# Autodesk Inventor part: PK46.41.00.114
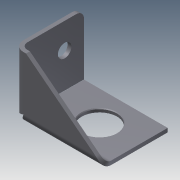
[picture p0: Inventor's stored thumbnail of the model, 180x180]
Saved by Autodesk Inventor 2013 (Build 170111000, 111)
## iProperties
Created: 2005-07
Part Number: PK46.41.00.114
Material: Steel, Mild
Document SubType Name: Листовой материал
Designer: PVitaliy
Manufacturer: Standard
Standards Organization: Custom
Density: 7.86 g/cm^3
Sheet Metal Rule: По умолчанию
Author: PVitaliy
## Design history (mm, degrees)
node "ФлнОтгиб1"
hole "Отверстие1" diameter "d11" = 10.5; stored, may be unused: countersink angle "d15" = 90 deg, drill point angle "d17" = 118 deg; dims "d9" = 15, "d10" = 20, "d12" = 6, "d13" = 4, "d14" = 2, "d16" = 3 (= Толщина)
feature "Вырез1" dims "d20" = 3 (= Толщина), "d21" = 0
node "Фланец1"
feature "Угловое скругление1" dims "d29" = 6
hole "Отверстие2" diameter "d32" = 27; stored, may be unused: countersink angle "d36" = 90 deg, drill point angle "d38" = 118 deg; dims "d30" = 23, "d31" = 30, "d33" = 6, "d34" = 4, "d35" = 2, "d37" = 3 (= Толщина)
feature "Угол1" dims "d39" = 12 (= Размер_высечки), "d40" = 5 (= Радиус_гибки), "d41" = 0.1, "d42" = 0, "Толщина" = 3
chamfer "Фаска1" distance "d43" = 0.5; stored, may be unused: second distance "d44" = 2, angle "d45" = 45 deg
body "Solid1"
sketch "Эскиз2"
  geometry: L1 (0, 0)-(68, 0); L2 (0, 0)-(0, 52)
  constraints: 4 end point, 1 horizontal, 1 vertical, 1 other
  dimensions: "d0" = 68 distance of L1.start L1.end; "d1" = 52 distance of L1.start L2.end
feature "Плакирование1" dims "d2" = 50, "d3" = 3 (= Ширина_просечки), "d5" = 6 (= Минимальный_остаток), "d7" = 5 (= Радиус_гибки), "d8" = 3, "Толщина" = 3
feature "Изгиб1" dims "d3" = 3 (= Ширина_просечки), "d4" = 1.5 (= Глубина_просечки), "d5" = 6 (= Минимальный_остаток), "d6" = 5 (= Радиус_гибки), "d7" = 5 (= Радиус_гибки), "d8" = 3, "Толщина" = 3, "Зазор_стыка" = 0.01
sketch "Эскиз3"
  geometry: L1 (0, 0)-(-60, 0) reference; L2 (0, 0)-(0, 50) reference; L3 (0, 50)-(-60, 50) reference; L4 (0, 5)-(-58, 50); L5 (-68, 0)-(-68, 50) reference
  constraints: 2 end point, 2 point on line
  dimensions: "d18" = 5 distance from line of L4.start L1; "d19" = 10 distance from line of L4.end L5
sketch "Эскиз4"
  geometry: L1 through (30, 0) direction (1, -1.85e-17); L2 (60, 0)-(60, 49); L3 (60, 49)-(0, 49); L4 through (0, 24.5) direction (0, -1)
  constraints: 6 end point, 1 horizontal, 1 perpendicular, 1 vertical
feature "Плакирование2" dims "d22" = 3 (= Ширина_просечки), "d24" = 6 (= Минимальный_остаток), "d26" = 49, "d27" = 90 deg, "d28" = 5 (= Радиус_гибки), "Толщина" = 3
feature "Изгиб2" dims "d22" = 3 (= Ширина_просечки), "d23" = 1.5 (= Глубина_просечки), "d24" = 6 (= Минимальный_остаток), "d25" = 5 (= Радиус_гибки), "d26" = 49, "d27" = 90 deg, "d28" = 5 (= Радиус_гибки), "Толщина" = 3, "Зазор_стыка" = 0.01
other parameters: "Радиус_гибки" = 5, "Ширина_просечки" = 3 (= Толщина), "Глубина_просечки" = 1.5 (= 0.5 x Толщина), "Размер_высечки" = 12 (= 4 x Толщина), "Минимальный_остаток" = 6 (= 2 x Толщина), "Радиус_перехода" = 5 (= Радиус_гибки), "JacobiRadiusSize" = 3 (= Толщина), "GapSize" = 3 (= Толщина)
